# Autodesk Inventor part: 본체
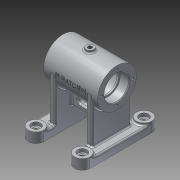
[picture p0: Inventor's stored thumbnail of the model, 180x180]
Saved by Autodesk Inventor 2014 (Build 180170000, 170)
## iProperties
Created: 2015-11
Part Number: 본체
Material: 알루미늄 6061
Document SubType Name: Modeling
Designer: 702
Density: 2.71 g/cm^3
Appearance: 알루미늄 - 평지
Mass: 359.154 g
Surface Area: 459.475 cm^2
Volume: 132.529 cm^3
Author: 702
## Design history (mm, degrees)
sketch "스케치1"
  geometry: C1 r 25 at (0, 0); C2 r 21 at (0, 0); 1 further point
  constraints: 2 centre point, 2 coincident
  dimensions: "d0" = 50 diameter of C1; "d1" = 42 diameter of C2
extrude "돌출1" new body sketch "스케치1" stored distance "d2" = 70; taper "d3" = 0 deg
extrude "돌출2" cut sketch "스케치1" stored distance "d4" = 42; taper "d5" = 0 deg
sketch "스케치2"
  geometry: C1 r 25 at (0, 0) reference; C2 r 16 at (0, 0); C3 r 14 at (0, 0)
  constraints: 2 centre point, 2 coincident
  dimensions: "d6" = 32 diameter of C2; "d7" = 28 diameter of C3
extrude "돌출3" cut sketch "스케치2" stored distance "d8" = 42; taper "d9" = 0 deg
extrude "돌출4" cut sketch "스케치2" distance "d10" = 12; taper "d11" = 0 deg
node "작업 평면1"
sketch "스케치3"
  geometry: L1 (-25, 0)-(-25, -68); L2 (25, 0)-(25, -68); L3 (-25, -68)-(25, -68); A1 r 25 centre (0, 0) between (-25, 0) and (25, 0) reference; 1 further point
  constraints: 6 end point, 2 point on circle, 2 tangent, 1 parallel, 1 perpendicular, 1 vertical
  dimensions: "d13" = 68 distance from line of L3 point (0, 0)
extrude "돌출5" join sketch "스케치3" distance "d14" = 8; taper "d15" = 0 deg
sketch "스케치4"
  geometry: L1 (0, 0)-(0, 50) reference; L2 (0, 50)-(-8, 50) reference; L3 (-8, 0)-(-8, 50) reference; L4 (0, 0)-(-8, 0) reference; L5 (-20, 65)-(-20, -15); L6 (0, -15)-(0, 65); A1 r 10 centre (-10, -15) between (-20, -15) and (0, -15); A2 r 10 centre (-10, 65) between (0, 65) and (-20, 65); 3 further points
  constraints: 4 end point, 4 point on circle, 4 tangent, 3 midpoint, 2 centre point, 1 horizontal alignment, 1 parallel, 1 perpendicular
  dimensions: "d16" = 20 distance between parallel lines of L6 L5; "d17" = 80 distance of A1.centre A2.centre
extrude "돌출6" join sketch "스케치4" distance "d18" = 10; taper "d19" = 0 deg
sketch "스케치5"
  geometry: C1 r 10 at (10, 65); C2 r 10 at (10, -15); A1 r 10 centre (10, -15) between (0, -15) and (20, -15) reference; A2 r 10 centre (10, 65) between (20, 65) and (0, 65) reference; 1 further point
  constraints: 2 centre point, 2 coincident, 1 equal radius
  dimensions: "d20" = 20 diameter of C1
extrude "돌출7" join sketch "스케치5" distance "d21" = 3; taper "d22" = 0 deg
sketch "스케치6"
  geometry: C1 r 10 at (0, 0) reference; C2 r 6 at (0, 0); C3 r 3 at (0, 0); C4 r 10 at (0, 80) reference; C5 r 6 at (0, 80); C6 r 3 at (0, 80); 1 further point
  constraints: 4 centre point, 4 coincident, 2 equal radius
  dimensions: "d23" = 12 diameter of C2; "d24" = 6 diameter of C3
extrude "돌출8" cut sketch "스케치6" distance "d25" = 4; taper "d26" = 0 deg
extrude "돌출9" cut sketch "스케치6" stored distance "d27" = 4; taper "d28" = 0 deg
sketch "스케치7"
  geometry: C1 r 16 at (0, 0) reference; 1 further point
  constraints: 1 vertical alignment
  dimensions: "d32" = 20 distance of C1.centre point (0, 20)
hole "구멍1" sketch "스케치7" at (0, 20) diameter "d33" = 3.242; stored, may be unused: countersink angle "d37" = 90 deg, drill point angle "d39" = 118 deg; dims "d34" = 8, "d35" = 4, "d36" = 2, "d38" = 10
sketch "스케치8"
  geometry: L1 (0, 0)-(25, 0); L2 (0, 0)-(14, -24.249); 1 further point
  constraints: 4 end point, 1 horizontal, 1 horizontal alignment, 1 other
  dimensions: "d43" = 60 deg angle of L1 L2; "d44" = 28 distance of L1.start L2.end
node "작업 평면2"
sketch "스케치9"
  geometry: C1 r 6 at (0, 0); 1 further point
  constraints: 1 centre point, 1 coincident
  dimensions: "d45" = 12 diameter of C1
extrude "돌출10" join sketch "스케치9" stored distance "d46" = 4; taper "d47" = 0 deg
hole "구멍2" diameter "d50" = 5.188; stored, may be unused: countersink angle "d54" = 90 deg, drill point angle "d56" = 118 deg; dims "d48" = 10, "d49" = 10, "d51" = 8, "d52" = 4, "d53" = 2, "d55" = 10
node "작업 평면3"
sketch "스케치10"
  geometry: C1 r 5 at (0, 0); 1 further point
  constraints: 1 centre point, 1 coincident
  dimensions: "d58" = 10 diameter of C1
extrude "돌출11" join sketch "스케치10" stored distance "d59" = 4; taper "d60" = 0 deg
hole "구멍3" diameter "d63" = 5.188; stored, may be unused: countersink angle "d67" = 90 deg, drill point angle "d69" = 118 deg; dims "d61" = 10, "d62" = 10, "d64" = 8, "d65" = 4, "d66" = 2, "d68" = 10
sketch "스케치11"
  geometry: L1 (-20, -45)-(20, -45); L2 (-20, 0)-(-20, -58) reference; L3 (20, 0)-(20, -58) reference; L4 (35, -25)-(-35, -25) reference; L5 (21, -21)-(-21, -21) reference; L6 (-20, -45)-(-20, -21); L7 (-20, -21)-(20, -21); L8 (20, -21)-(20, -45); L9 (-8, -31.5)-(8, -31.5); L10 (8, -38.5)-(-8, -38.5); L11 (33, -68)-(27, -68) reference; A1 r 3.5 centre (8, -35) between (8, -38.5) and (8, -31.5); A2 r 3.5 centre (-8, -35) between (-8, -31.5) and (-8, -38.5); 3 further points
  constraints: 12 end point, 6 point on line, 4 point on circle, 4 tangent, 2 centre point, 2 midpoint, 2 vertical alignment, 1 collinear, 1 horizontal, 1 parallel, 1 perpendicular
  dimensions: "d70" = 20 distance between parallel lines of L4 L1; "d71" = 3.5 radius of A1; "d72" = 23 dimension on A1 A2; "d73" = 33 distance from line of L11 A1.centre
extrude "돌출12" join sketch "스케치11" stored distance "d74" = 8; taper "d75" = 0 deg
node "작업 평면4"
sketch "스케치12"
  geometry: 2 further points
  constraints: 2 coincident, 1 other
feature "엠보싱1" sketch "스케치12" dims "d13" = 68, "d76" = 0.5, "d77" = 0
fillet "모깎기1" dims "d78" = 3, "d79" = 2
chamfer "모따기2" distance "d80" = 1; stored, may be unused: second distance "d81" = 2, angle "d82" = 45 deg
fillet "모깎기2" dims "d83" = 0.3, "d84" = 2
node "솔리드1"
pattern_circular "원형 패턴1" dims angle "d41" = 360 deg
mirror "대칭1"
other parameters: "d57" = 28
